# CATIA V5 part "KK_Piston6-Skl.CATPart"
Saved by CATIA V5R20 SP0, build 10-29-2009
Part number: Piston6-Skl
Bounding box of the stored display mesh (mm): x -99.999 to -63.303, y -13.696 to -0.34, z 0 to 100
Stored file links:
  G:\Khaled_CFAO_2011\ST2M\ST2M_GR1\msallin\Khaled\Version_Finale\KK_Piston6-Skl.CATPart
  C:\Users\Mathieu\Desktop\Think Motion\JOUG-MELEE2.CATProduct
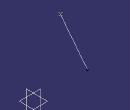
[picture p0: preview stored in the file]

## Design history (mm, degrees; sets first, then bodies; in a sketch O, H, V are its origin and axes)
External parameters (linked from other documents)
  `External.Taille du joug` = 100 mm
Set1
  Point1: linked copy from another document
  Point2: linked copy from another document
Set2
  Line1: type PtPt, FirstPoint Point1, SecondPoint Point2
  Point3: (0, 0, 0), relative to Point1
Body1 (main body)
